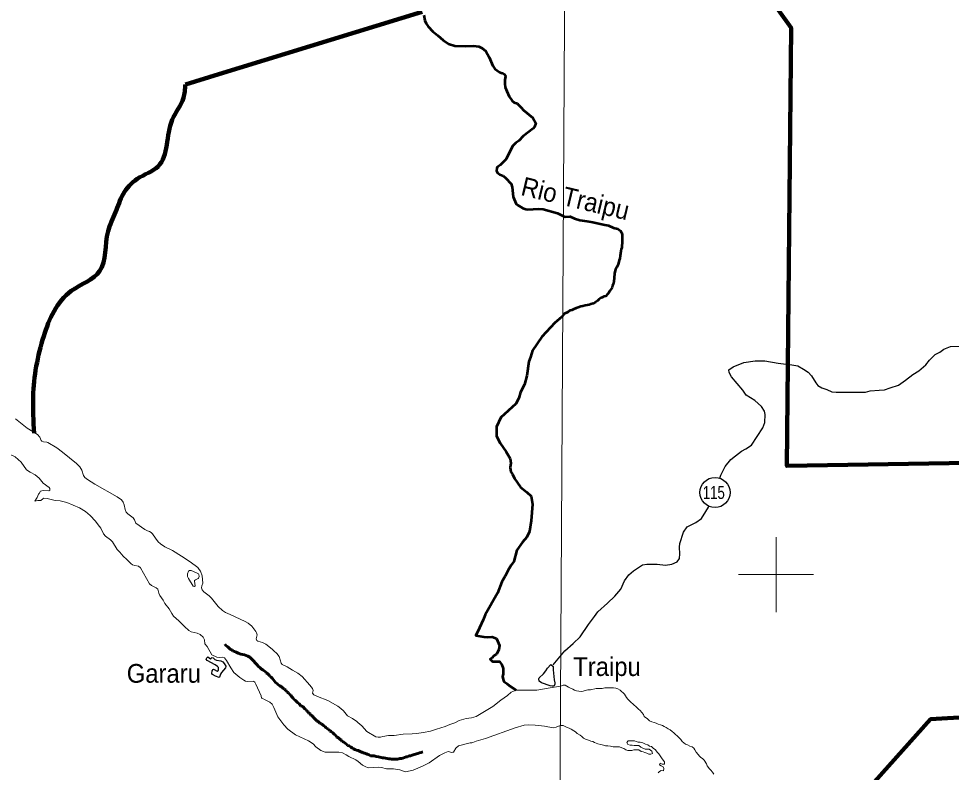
# Model space of a CAD drawing. Extents: x 553962 to 842807, y 8883888 to 9032388.
# Drawn here: x 704795 to 729677, y 8894722 to 8914830 of the extents above; entities that cross this region are included whole.
import ezdxf
from ezdxf.enums import TextEntityAlignment as Align

# ---------------------------------------------------------------- set-up
doc = ezdxf.new("R2010")
doc.units = 0
doc.header["$LTSCALE"] = 200
doc.linetypes.add('LONG_DASH_SHORT_DASH', pattern=[9.9, 6, -1.2, 1.5, -1.2])
for name, color, linetype, lineweight in [('1', 7, 'Continuous', 13), ('12', 7, 'Continuous', 25), ('2', 7, 'Continuous', 13), ('21', 7, 'Continuous', 25), ('24', 7, 'Continuous', 25), ('25', 7, 'Continuous', 13), ('48', 7, 'Continuous', 25), ('7', 7, 'LONG_DASH_SHORT_DASH', 60), ('9', 7, 'Continuous', 90)]:
    doc.layers.add(name, color=color, linetype=linetype, lineweight=lineweight)
doc.layers.add('41', color=7, linetype='Continuous')
doc.layers.add('49', color=7, linetype='Continuous')

msp = doc.modelspace()

# ---------------------------------------------------------------- linework, layer by layer
at = {"layer": '1'}
msp.add_lwpolyline([(719978.9, 9023574.5), (719561.6, 8949232.2), (719215.6, 8890710.6)], dxfattribs=at)
at = {"layer": '12'}
for points in [[(727039.6, 8904864.2), (727284.1, 8904868.9), (727391.1, 8904868.7), (727508.4, 8904899), (727747.9, 8904919), (727890.6, 8904928.9), (728048.7, 8904984.6), (728268, 8905055.5), (728451.9, 8905187.7), (728651.2, 8905340.1), (728809.4, 8905436.6), (728993.4, 8905594.2), (729095.8, 8905716.2), (729249.1, 8905868.8), (729371.7, 8905934.8), (729473.8, 8906011), (729657.5, 8906082), (729896.9, 8906091.7)], [(723502.8, 8902567), (723531.6, 8902649.7), (723639.5, 8902883.8), (723793, 8903072), (723920.7, 8903168.5), (724079.1, 8903290.5), (724191.4, 8903356.5), (724349.7, 8903453), (724652, 8903916), (724698.3, 8904058.6), (724714.4, 8904272.5), (724689.2, 8904354.1), (724613.3, 8904481.5), (724430.5, 8904644.9), (724201.8, 8904787.9), (724110.5, 8904915.5), (723811.3, 8905272.6), (723745.5, 8905389.9), (723740.7, 8905461.2), (723858.1, 8905542.5), (724143.8, 8905659.1), (724444.6, 8905699.3), (724704.4, 8905698.9), (725060.7, 8905637.1), (725417.2, 8905595.7), (725585.2, 8905564.8), (725732.6, 8905477.9), (725859.7, 8905396.2), (725945.9, 8905304.3), (726062.4, 8905115.6), (726113.1, 8905039.1), (726219.8, 8904977.8), (726352.1, 8904931.7), (726489.4, 8904870.3), (726601.5, 8904865), (727039.6, 8904864.2)], [(719051.7, 8897586.9), (719362.5, 8897965.7), (719587.4, 8898163.9), (719771.5, 8898341.9), (719996.8, 8898667.5), (720160.6, 8898881.1), (720247.7, 8899003.2), (720508.3, 8899237.1), (720697.5, 8899420.1), (720856.1, 8899608.3), (720953.7, 8899827.2), (721076.6, 8899989.9), (721194.2, 8900101.8), (721434.2, 8900254.2), (721551.4, 8900279.4), (721826.5, 8900273.8), (722050.5, 8900248), (722223.9, 8900278.2), (722366.7, 8900339.1), (722428.2, 8900425.6), (722433.7, 8900552.9), (722424.2, 8900726.1), (722429.7, 8900828), (722532.7, 8901133.4), (722624.9, 8901275.9), (722864.7, 8901387.5), (723007.8, 8901494.2), (723130.7, 8901677.4), (723197.4, 8901799.6), (723209.3, 8901823.1)]]:
    msp.add_lwpolyline(points, dxfattribs=at)
at = {"layer": '2'}
for p, q in [((725000, 8899000), (725000, 8901000)), ((724000, 8900000), (726000, 8900000))]:
    msp.add_line(p, q, dxfattribs=at)
at = {"layer": '21'}
for points in [[(710323, 8897547.4), (710310.6, 8897510.9), (710262.7, 8897448.5), (710205.4, 8897388.1), (710179.6, 8897340.9), (710149.4, 8897265.1), (710140.8, 8897256.9), (710043.9, 8897288.4), (709961.7, 8897329.1), (709947.6, 8897363.1), (709961.6, 8897429.2), (709984.2, 8897470), (709989.6, 8897472.6), (710012.7, 8897467.5), (710090.3, 8897425.2), (710122.4, 8897447.6), (710126, 8897519.8), (710103.3, 8897545.3), (710035.6, 8897588.8), (709826.1, 8897706.4), (709795.6, 8897744), (709810.8, 8897781.5), (709838, 8897800.1), (709914.9, 8897754.6), (709934.2, 8897760.9), (709942.3, 8897776.2), (709957.1, 8897785.6), (709980.8, 8897774.5), (710029.3, 8897733.8), (710072, 8897710.7), (710184.3, 8897701.5), (710239.2, 8897671.8), (710278.2, 8897623.4), (710322, 8897552.2)], [(718993.1, 8897599.9), (719057.4, 8897544.6), (719055.9, 8897461.4), (719085.3, 8897192.5), (719103.1, 8897108.8), (719098.1, 8897076.1), (719079.4, 8897033), (719065.5, 8897020), (719028.2, 8897020.1), (718974.7, 8897034.1), (718746.2, 8897111.7), (718679.7, 8897153.1), (718671.6, 8897221.2), (718685, 8897240.1), (718799.2, 8897348.2), (718862.4, 8897430.9), (718906.6, 8897502.9)]]:
    msp.add_lwpolyline(points, close=True, dxfattribs=at)
at = {"layer": '24', "lineweight": 53}
for points in [[(715607.3, 8914926.5), (715630.8, 8914782.1), (715664.2, 8914698.4), (715720.4, 8914621.3), (715841.4, 8914484.8), (715976.3, 8914382.9), (716121.9, 8914251.7), (716262.7, 8914158.2), (716430.6, 8914102.4), (716723.3, 8914098.2), (716931, 8914106.3), (717067.3, 8914089.8), (717160, 8914040), (717258.6, 8913960.8), (717350.2, 8913798.9), (717444.9, 8913569.6), (717500.7, 8913495.3), (717620.4, 8913403.7), (717696.9, 8913374.6), (717753.4, 8913338.3), (717771.3, 8913315.3), (717779.7, 8913284.7), (717767.4, 8913198.7), (717765.2, 8913088.6), (717776, 8913003.3), (717816.4, 8912891.5), (717881.6, 8912752), (717959.7, 8912633.8), (718012.2, 8912595.1), (718103.9, 8912566), (718108.4, 8912552.9), (718200.6, 8912462.7), (718263.8, 8912388), (718510.9, 8912180.7), (718595.9, 8912042.5), (718559.6, 8911942), (718525.1, 8911895.3), (718256.7, 8911695.7), (718139.8, 8911569.1), (718058.8, 8911518.2), (717971, 8911425.9), (717799.8, 8911079.5), (717637.2, 8910919.9), (717559.9, 8910863.9), (717548.7, 8910844.9), (717546.6, 8910765.8), (717564.2, 8910723.9), (717629.5, 8910673.2), (717717.9, 8910632.5), (717786.1, 8910583.9), (717932.5, 8910426.1), (717961.9, 8910338.5), (717987.1, 8910076.6), (718063.3, 8909892.7), (718110.2, 8909851.7), (718240.9, 8909774.5), (718323.8, 8909744.9), (718380.9, 8909735.3), (718665.9, 8909753.1), (718783.6, 8909747.4), (719169.5, 8909639.4), (719326.4, 8909556.3)], [(719326.4, 8909556.3), (719371.3, 8909542.5), (719371.3, 8909542.5), (719504.5, 8909548.1), (719504.5, 8909548.1), (719504.5, 8909548.1), (719626.5, 8909498.2)], [(719626.5, 8909498.2), (719765.2, 8909453.8), (719765.2, 8909453.8), (719765.2, 8909453.8), (719765.2, 8909453.8), (719948.4, 8909426.1), (719948.4, 8909426.1), (719948.4, 8909426.1), (720114.8, 8909398.4), (720114.8, 8909398.4), (720114.8, 8909398.4), (720392.3, 8909337.4), (720392.3, 8909337.4), (720392.3, 8909337.4), (720392.3, 8909337.4), (720531, 8909309.6), (720531, 8909309.6), (720531, 8909309.6), (720664.2, 8909248.6), (720780.7, 8909226.5), (720848.9, 8909167.8), (720879.1, 8909126.9), (720899.1, 8909075.8), (720898.7, 8909024.9), (720898.3, 8908963.8), (720892.8, 8908897.6), (720892.3, 8908831.3), (720886.9, 8908780.4), (720886.5, 8908724.4), (720865.8, 8908678.7), (720860.4, 8908622.7), (720854.9, 8908561.6), (720844.3, 8908500.6), (720828.6, 8908434.4), (720818, 8908383.6), (720797.2, 8908307.3), (720781.6, 8908256.4), (720750.7, 8908200.6), (720714.6, 8908139.7), (720699, 8908078.7), (720693.5, 8908027.8), (720680.1, 8907917.9)], [(720680.1, 8907917.9), (720671.8, 8907819.1), (720661.2, 8907768.2), (720640.5, 8907712.3), (720624.9, 8907661.5), (720594, 8907605.6), (720558.1, 8907560), (720532.3, 8907509.3), (720496.4, 8907468.7), (720460.5, 8907428.2), (720409.6, 8907413.3), (720363.7, 8907393.2), (720312.7, 8907373.1), (720276.8, 8907337.7), (720241, 8907302.3), (720179.7, 8907267), (720118.4, 8907231.8), (720062.3, 8907216.8), (720016.4, 8907196.8), (719965.5, 8907181.8), (719909.5, 8907177.1), (719843.3, 8907162.2), (719792.3, 8907152.3), (719720.9, 8907122.2), (719664.9, 8907107.3), (719603.6, 8907077.1), (719552.6, 8907057.1), (719496.6, 8907042.2), (719445.4, 8907001.8), (719343.4, 8906951.5), (719283.6, 8906877)], [(719283.6, 8906877), (719100.8, 8906711), (718751.9, 8906345.6), (718502.7, 8905980.3), (718452.8, 8905797.7), (718403, 8905681.4), (718353.1, 8905299.5), (718286.7, 8905067), (718187, 8904867.8), (718137.2, 8904701.7), (718054.1, 8904552.2), (717859.9, 8904374.3), (717854.7, 8904369.6)], [(717854.7, 8904369.6), (717655.3, 8904186.9), (717539, 8903937.8), (717539, 8903688.8), (717638.7, 8903506.1), (717804.9, 8903273.6), (717904.6, 8903091), (717921.2, 8902974.7), (717904.6, 8902858.5), (717921.2, 8902742.3), (717971.1, 8902675.9), (718020.9, 8902559.6), (718187, 8902327.1), (718353.2, 8902194.3), (718469.5, 8902094.7), (718502.7, 8901878.8), (718469.5, 8901430.4), (718419.6, 8901148.2), (718353.2, 8900998.7), (718236.8, 8900865.9), (718087.3, 8900650), (718004.2, 8900351.1), (717937.8, 8900251.5), (717854.7, 8900118.6), (717771.7, 8899952.6), (717688.6, 8899803.1), (717572.3, 8899504.2), (717240, 8898923), (717190.1, 8898790.2), (717090.4, 8898574.3), (716990.8, 8898375.1), (717206.8, 8898341.9), (717289.8, 8898325.2), (717422.7, 8898341.9), (717539, 8898292), (717622.1, 8898109.4), (717605.5, 8897993.1), (717539, 8897876.9), (717472.6, 8897827.1), (717422.7, 8897777.3), (717372.9, 8897744.1), (717439.4, 8897677.6), (717622.1, 8897677.6), (717688.6, 8897594.6), (717721.8, 8897495), (717721.8, 8897395.3), (717721.8, 8897345.5), (717705.2, 8897279.1), (717721.8, 8897196.1), (717738.4, 8897146.3), (717821.5, 8897096.4), (717888, 8897030), (718070.7, 8896913.8)]]:
    msp.add_lwpolyline(points, dxfattribs=at)
at = {"layer": '25'}
for points in [[(704709.8, 8904149.5), (705025.3, 8903904.5), (705294.1, 8903731.4), (705355.9, 8903661.9), (705397.8, 8903579.9), (705416.3, 8903559.4), (705456.6, 8903537.1), (705545.2, 8903528.8), (705574.6, 8903518.8), (705812.1, 8903380.7), (705964.1, 8903265.1), (706335.8, 8902958.3), (706429, 8902870.5), (706478.4, 8902782.6), (706522.3, 8902644.6), (706561.4, 8902592.6), (706627.5, 8902537.3), (706829.4, 8902410.4), (707426.7, 8902069.6), (707536.7, 8901989.7), (707580.8, 8901930.1), (707613.5, 8901857.8), (707638, 8901734), (707661.4, 8901666.3), (707707.1, 8901616.1), (707849, 8901513.6), (707889.3, 8901456.4), (707921.2, 8901374.1), (708164.6, 8901203.2), (708234, 8901164.4), (708282.6, 8901144)], [(705417, 8902230.5), (705468.7, 8902243.1), (705601.7, 8902236.3), (705626.1, 8902249.9), (705630.1, 8902294), (705613.1, 8902318.7), (705450.5, 8902433.4), (705338.6, 8902571.8), (705237.8, 8902662.7), (705098.5, 8902732.8), (705008.4, 8902794.2), (704859.8, 8902995.3), (704700.7, 8903136.3), (704418.9, 8903273.5)], [(705223.5, 8901956.6), (705285.9, 8902055.5), (705327.2, 8902145.4), (705340, 8902163.9), (705340, 8902163.9)], [(705340, 8902163.9), (705380.2, 8902221.5), (705417, 8902230.5)], [(706917, 8901328.8), (706845.7, 8901419), (706706.3, 8901570.6), (706577.5, 8901683.7), (706418, 8901776), (706077.6, 8901924.8), (705902.1, 8901964.8), (705769.4, 8901975.3), (705559.8, 8902024.1), (705462.6, 8902034.1), (705436.9, 8902022.7), (705383.9, 8901976.1), (705305.7, 8901975.9), (705223.5, 8901956.6)], [(708884.8, 8898960.2), (708812.9, 8899081.1), (708692, 8899230.3), (708649.9, 8899313.3), (708562.2, 8899440.2), (708534.2, 8899502.9), (708503.8, 8899608.4), (708465.9, 8899644.1), (708336.8, 8899710.3), (708284.4, 8899750.1), (708047.8, 8900175.7), (707990.8, 8900226.5), (707897.1, 8900236.8), (707831, 8900260), (707784.3, 8900295.7), (707679.2, 8900403.7), (707579.3, 8900485.4), (707498.4, 8900600.3), (707426.9, 8900668.2), (707296.2, 8900870.2), (707244.9, 8900923.6), (707114.9, 8901025.9), (707060.8, 8901088.8), (706991.1, 8901234.8), (706917, 8901328.8)], [(708282.6, 8901144), (708331.2, 8901123.5), (708369.6, 8901088.6), (708444.9, 8900971.6), (708520.8, 8900871.2), (708577.2, 8900819.4), (708690.2, 8900735.5), (708901.9, 8900638.8), (709137.2, 8900490.7)], [(709137.2, 8900490.7), (709372.6, 8900342.6), (709571.9, 8900187.3), (709610.7, 8900136.5)], [(709610.7, 8900136.5), (709649.5, 8900085.8), (709687.8, 8899966.6), (709696.9, 8899867.4)], [(709696.9, 8899867.4), (709706, 8899768.3), (709680, 8899695), (709673.6, 8899642.5), (709691.5, 8899588), (709738.8, 8899535.9), (709875.6, 8899429.5), (709875.6, 8899429.5), (709939.8, 8899367.7), (710112.9, 8899145), (710229.9, 8899043.2), (710316.3, 8898983), (710434.5, 8898930.1)], [(709950.2, 8897853.8), (709826.5, 8898078.7), (709765, 8898154.3), (709755.6, 8898257.5), (709714.4, 8898328.8), (709634.6, 8898396.5), (709559.8, 8898439.4), (709395, 8898473.4), (709333.8, 8898506.8), (709214.9, 8898614.3), (709070.8, 8898765.5), (708925, 8898892.5), (708884.8, 8898960.2)], [(710434.5, 8898930.1), (710835, 8898750.5), (710918.4, 8898699.6), (711013.8, 8898623.8), (711070, 8898553.2)], [(711070, 8898553.2), (711126.2, 8898482.6), (711144.3, 8898448), (711158.3, 8898389.2), (711130.3, 8898282.3), (711152.8, 8898240), (711175.8, 8898222.2), (711302.1, 8898183.8), (711391.3, 8898138.3), (711554.3, 8898011), (711603.7, 8897966)], [(711603.7, 8897966), (711680.2, 8897896.3), (711746, 8897808.5), (711799.4, 8897633.4), (711822.1, 8897601.2), (711960, 8897533.9), (712103.8, 8897448.7)], [(710692.4, 8897249.1), (710533.9, 8897388.5), (710451.3, 8897511.8), (710342.9, 8897708), (710286.4, 8897777.2), (710220.4, 8897794.9), (710145.3, 8897789.3), (710079.5, 8897794.7), (709950.2, 8897853.8)], [(712103.8, 8897448.7), (712242.6, 8897366.3), (712359.3, 8897283.4), (712565.7, 8897048.4), (712631.8, 8896958.1), (712647.9, 8896909.4), (712637.9, 8896831.9), (712665.2, 8896790.9), (712768.3, 8896741.4), (713044.9, 8896638.8), (713311.2, 8896489.3), (713385.5, 8896424.1)], [(711124.5, 8897078.8), (711093, 8897127.9), (711068.7, 8897147.8), (711049.5, 8897152.8), (710908.8, 8897146.9), (710849.4, 8897155.7), (710797.6, 8897180.7), (710692.4, 8897249.1)], [(712525.7, 8895564.3), (712179.3, 8895726.8), (711977.5, 8895873.7), (711872.3, 8895986), (711707.5, 8896200.3), (711600.3, 8896454.3), (711553.8, 8896536.9), (711494.9, 8896598.8), (711354.3, 8896661.8), (711292.1, 8896701.3), (711270.5, 8896704.9), (711261.3, 8896763.5), (711124.5, 8897078.8)], [(716671.9, 8896141.4), (716736, 8896160), (716876.8, 8896172.9), (716996.8, 8896216.3), (717443.2, 8896481.3), (717658.9, 8896651.8), (717833.2, 8896772.8), (717934, 8896865.6), (718070.7, 8896913.8), (718220.3, 8896913.8), (718619, 8896913.8), (718918.1, 8896963.6), (719252.2, 8897020.3)], [(719252.2, 8897020.3), (719320.1, 8897049.2), (719376, 8897048.8), (719416.5, 8897018), (719467.2, 8896997.3), (719517.9, 8896971.5), (719578.7, 8896940.5), (719624.3, 8896914.8), (719680.1, 8896894), (719736.1, 8896888.6), (719797.1, 8896883.1), (719858.1, 8896887.8), (719909.1, 8896907.8), (719980.4, 8896922.7), (720046.6, 8896927.3), (720199.4, 8896962), (720255.3, 8896961.7), (720306.2, 8896961.3), (720362.2, 8896961), (720428.4, 8896980.9), (720479.3, 8896980.6), (720540.3, 8896980.2), (720606.4, 8896979.8), (720667.5, 8896979.4), (720723.3, 8896968.8), (720779.1, 8896948.1), (720845, 8896917.1), (720880.4, 8896881.2), (720920.8, 8896845.3), (720956.2, 8896809.4)], [(720956.2, 8896809.4), (720981.3, 8896763.4), (721006.4, 8896717.4), (721046.8, 8896676.4), (721082.2, 8896635.4), (721127.7, 8896594.4), (721188.3, 8896538), (721289.5, 8896455.8), (721329.8, 8896404.6), (721375.3, 8896368.7), (721420.8, 8896322.5), (721461, 8896261.2), (721486.2, 8896215.2), (721567.1, 8896148.4), (721627.8, 8896097.1), (721683.5, 8896071.3), (721749.5, 8896050.5), (721805.3, 8896034.8), (721856, 8896009), (721916.9, 8895988.3), (721972.7, 8895967.5), (722018.4, 8895946.9), (722069, 8895921.1), (722119.7, 8895885.1), (722175.4, 8895854.2), (722231, 8895808), (722271.5, 8895772), (722312, 8895741.2), (722367.5, 8895689.9), (722402.9, 8895654), (722463.5, 8895597.6), (722493.7, 8895546.5), (722584.8, 8895474.6), (722635.5, 8895453.9), (722701.4, 8895417.8), (722762.3, 8895402.1), (722802.7, 8895366.2), (722832.9, 8895320.2), (722873.2, 8895263.9), (722923.6, 8895197.3), (722953.8, 8895151.3), (722994.3, 8895120.5), (723039.9, 8895089.6), (723085.4, 8895048.6), (723145.7, 8894951.4), (723165.7, 8894895.3), (723221.1, 8894818.5), (723261.6, 8894782.6), (723301.9, 8894726.3), (723337.1, 8894675.1)], [(713385.5, 8896424.1), (713459.8, 8896359), (713569.8, 8896225.6), (713696.9, 8896155.1), (713818.3, 8896075.1), (713842, 8896053.8)], [(715944.9, 8895871), (716177.3, 8895944.3), (716297, 8895998.6), (716434.9, 8896046.3), (716544.4, 8896104.3), (716671.9, 8896141.4)], [(713842, 8896053.8), (713946.1, 8895960.1), (714080.1, 8895815.7), (714321.1, 8895672.2), (714384.5, 8895659.7), (714451.9, 8895662.4), (714514.6, 8895674.6)], [(719242.1, 8895974.6), (719137.8, 8895926.7), (719051.9, 8895910.8), (718819, 8895950.7), (718570.6, 8895982.3), (718406.7, 8895992.1), (718284.1, 8895976.8), (718038.4, 8895905.8), (717250.7, 8895623.3), (716998.4, 8895554.6), (716915, 8895518.1), (716881.8, 8895513.8)], [(721516.7, 8895476.3), (721445.7, 8895507.4), (721379.7, 8895523.1), (721323.7, 8895523.4), (721273, 8895544.1), (721222.2, 8895559.7), (721151.1, 8895560.2), (721054.4, 8895560.8), (721023.6, 8895520.3), (721043.6, 8895469.2), (721104.5, 8895443.3), (721160.4, 8895443), (721211.3, 8895442.7), (721277.4, 8895442.2), (721343.5, 8895436.7), (721394.1, 8895395.6), (721444.7, 8895364.7), (721505.6, 8895344), (721561.5, 8895338.5), (721612.4, 8895338.2), (721688.3, 8895286.8), (721708.2, 8895225.5), (721657.3, 8895210.6), (721606.4, 8895210.9), (721555.7, 8895231.6), (721499.9, 8895252.3), (721454.2, 8895273), (721398.3, 8895278.4), (721342.7, 8895319.6), (721276.6, 8895325.1), (721205.3, 8895320.4), (721154.4, 8895305.5), (721098.4, 8895300.7), (721042.5, 8895301.1), (720996.9, 8895326.9), (720941.1, 8895357.8), (720890.4, 8895378.5), (720824.4, 8895399.3), (720773.6, 8895399.6), (720722.7, 8895399.9), (720656.6, 8895405.4), (720580.4, 8895421.2), (720509.3, 8895426.8), (720448.2, 8895427.2), (720397.5, 8895447.9), (720326.5, 8895468.7), (720250.3, 8895484.5), (720158.9, 8895515.6), (720113.3, 8895541.4), (720062.6, 8895557), (719996.6, 8895577.8), (719920.5, 8895608.8), (719864.8, 8895634.7), (719819.3, 8895675.7), (719778.8, 8895711.6), (719692.7, 8895758), (719647.2, 8895799.1), (719606.7, 8895829.9), (719535.8, 8895876.2), (719480.1, 8895902), (719429.3, 8895917.6), (719373.6, 8895948.5), (719317.8, 8895969.3), (719266.9, 8895969.6), (719242.1, 8895974.6)], [(714514.6, 8895674.6), (714664.7, 8895703.8), (714810.4, 8895708.8), (715055.3, 8895739.1), (715289.1, 8895748.2), (715407.8, 8895761.9)], [(715407.8, 8895761.9), (715591.5, 8895783.2), (715777.5, 8895818.2), (715944.9, 8895871)], [(713532.7, 8895186.2), (713435.1, 8895242.8), (713335.4, 8895258.7), (712968.6, 8895262), (712859.7, 8895301.9), (712725.3, 8895401.6), (712648.5, 8895483.1), (712525.7, 8895564.3)], [(716881.8, 8895513.8), (716841.2, 8895508.6), (716533, 8895427), (716458.2, 8895365.9), (716394.5, 8895260), (716374.9, 8895256.9)], [(721852.2, 8894705), (721893.1, 8894740.4), (721934, 8894770.7), (721995, 8894765.2), (722010.6, 8894821.2), (721985.5, 8894867.2), (721934.8, 8894893), (721889.3, 8894923.8), (721909.9, 8894969.5), (721960.6, 8894943.7), (722021.6, 8894943.3), (722027.1, 8895004.4), (721986.8, 8895050.5), (721946.5, 8895106.8), (721911.2, 8895163.1), (721871, 8895219.4), (721825.5, 8895260.4), (721780.1, 8895321.8), (721719.4, 8895368.1), (721679, 8895409.1), (721628.2, 8895424.7), (721577.6, 8895455.6), (721516.7, 8895476.3)], [(715039.1, 8894760), (714963.6, 8894786.5), (714790.6, 8894820), (714606.1, 8894818.8), (714473.2, 8894853.3), (714404.1, 8894859.6), (714116.9, 8894843.6), (714034.5, 8894876.8), (713967, 8894916.7), (713850.5, 8895013.2), (713789.1, 8895053.9), (713604, 8895144.8), (713532.7, 8895186.2)], [(716374.9, 8895256.9), (716350.2, 8895253.1), (716257.5, 8895274.6), (716162.3, 8895243), (716023.3, 8895172.8), (715744.1, 8894976.4), (715570.5, 8894886.6), (715322, 8894784.1), (715114.6, 8894733.5), (715039.1, 8894760)]]:
    msp.add_lwpolyline(points, dxfattribs=at)
msp.add_lwpolyline([(709580.3, 8899889.8), (709596.2, 8899906.3), (709606, 8899943.5), (709599.7, 8899997.3), (709588.6, 8900017.3), (709459.5, 8900083.7), (709393.7, 8900104.9), (709351.6, 8900105.7), (709323, 8900086.1), (709294.9, 8900014.3), (709301.9, 8899949.1), (709327.1, 8899890.5), (709454.5, 8899688.2), (709485.7, 8899677.3), (709503.8, 8899701.2), (709483.4, 8899821.2), (709487.6, 8899841.5), (709510.1, 8899860.5)], close=True, dxfattribs=at)
at = {"layer": '48'}
msp.add_circle((723371.8, 8902188.1), 401.3, dxfattribs=at)
at = {"layer": '7'}
for points in [[(711474.4, 8897314.1), (711433.6, 8897355), (711398, 8897378), (711370, 8897413.8), (711308.9, 8897454.7), (711270.7, 8897477.7), (711230, 8897521.1), (711189.3, 8897549.2), (711148.6, 8897600.3), (711112.9, 8897631), (711056.9, 8897694.9), (711016.2, 8897746.1), (710965.3, 8897792.1), (710911.8, 8897817.6), (710817.7, 8897856), (710718.5, 8897873.8), (710647.2, 8897904.5), (710598.8, 8897925), (710555.6, 8897945.4), (710507.2, 8897965.9), (710481.8, 8897986.3), (710448.7, 8898001.7), (710413.1, 8898034.9), (710374.9, 8898073.2), (710334.2, 8898098.8), (710296.3, 8898144.4)], [(712701.2, 8896140.8), (712675.8, 8896166.4), (712632.5, 8896220.1), (712599.4, 8896243.1), (712581.6, 8896276.3), (712546, 8896294.2), (712525.6, 8896327.4), (712487.4, 8896347.9), (712467.1, 8896388.8), (712431.4, 8896414.3), (712375.4, 8896475.7), (712327.1, 8896498.7), (712276.2, 8896547.2), (712230.3, 8896585.6), (712176.9, 8896636.7), (712146.3, 8896664.8), (712110.7, 8896708.3), (712075.1, 8896746.6), (712052.2, 8896784.9), (712016.5, 8896805.4), (711996.2, 8896843.7), (711960.5, 8896861.6), (711924.9, 8896910.2), (711889.3, 8896928.1), (711866.3, 8896958.8), (711830.7, 8896976.7), (711795.1, 8897009.9), (711759.5, 8897027.8), (711718.7, 8897061), (711695.8, 8897081.5), (711657.6, 8897112.1), (711619.5, 8897158.2), (711594, 8897186.3), (711555.8, 8897232.3), (711532.9, 8897257.8), (711497.3, 8897291.1), (711474.4, 8897314.1)], [(715172.3, 8895138.8), (715134.1, 8895136.3), (715085.8, 8895115.8), (715047.6, 8895103.1), (715004.4, 8895095.4), (714963.7, 8895087.7), (714935.7, 8895082.6), (714900.1, 8895077.5), (714841.5, 8895077.5), (714803.3, 8895077.5), (714762.7, 8895077.5), (714739.7, 8895077.5), (714701.6, 8895080), (714673.6, 8895082.6), (714625.2, 8895090.3), (714582, 8895097.9), (714541.3, 8895105.6), (714503.1, 8895113.3), (714464.9, 8895120.9), (714431.8, 8895128.6), (714391.1, 8895136.3), (714332.6, 8895143.9), (714279.2, 8895159.3), (714230.8, 8895166.9), (714185, 8895166.9), (714144.3, 8895187.4), (714096, 8895205.3), (714055.2, 8895220.6), (714034.9, 8895225.7), (714004.3, 8895241.1), (713984, 8895246.2), (713945.8, 8895264.1), (713922.9, 8895269.2), (713889.8, 8895289.6), (713851.6, 8895307.5), (713808.4, 8895310.1), (713762.6, 8895328), (713732, 8895345.9), (713693.9, 8895376.5), (713653.1, 8895391.9), (713612.4, 8895425.1), (713569.2, 8895440.4), (713541.2, 8895471.1), (713503, 8895496.7), (713467.3, 8895527.3), (713429.2, 8895547.8), (713403.7, 8895581), (713370.6, 8895601.5), (713324.8, 8895642.4), (713273.9, 8895670.5), (713248.5, 8895716.5), (713210.3, 8895739.5), (713177.2, 8895775.3), (713131.4, 8895811.1), (713098.3, 8895831.5), (713057.6, 8895869.9), (713032.1, 8895885.2), (712991.4, 8895918.4), (712968.5, 8895933.8), (712930.3, 8895972.1), (712871.8, 8896020.7), (712828.5, 8896033.5), (712787.8, 8896074.3), (712747.1, 8896094.8), (712701.2, 8896140.8)], [(715575.1, 8895269.4), (715574.3, 8895269.2), (715533.6, 8895253.9), (715487.8, 8895238.5), (715444.5, 8895225.8), (715347.8, 8895195.1), (715294.4, 8895177.2), (715248.6, 8895164.4), (715200.3, 8895159.3), (715172.3, 8895138.8)]]:
    msp.add_lwpolyline(points, dxfattribs=at)
at = {"layer": '9'}
for p, q in [((710134.6, 8913345.1), (715561.4, 8915010.8)), ((709242.2, 8913071.2), (710135.7, 8913345.4))]:
    msp.add_line(p, q, dxfattribs=at)
for points in [[(741371.9, 8898310.2), (736775.3, 8899194.4), (730163.4, 8902976.8), (725291.2, 8902898), (725401.2, 8914588.3), (719613.1, 8922670.1)], [(724638.9, 8891123.6), (729122.2, 8896139.1), (740717.5, 8896813.6), (741371.9, 8898310.2)]]:
    msp.add_lwpolyline(points, dxfattribs=at)
msp.add_spline([(705207.9, 8903769.6), (705180.7, 8904747.4), (705463.8, 8906360), (706198.7, 8907564.6), (706955.5, 8908091.1), (707178.8, 8909156.3), (707379.5, 8909664.2), (707580.3, 8910146.8), (707959.3, 8910554.8), (708516.4, 8910888.1), (708891.3, 8912131.7), (709193.2, 8912716.3), (709242.2, 8913071.2)], degree=3, dxfattribs=at)

# ---------------------------------------------------------------- texts
at = {"layer": '41', "width": 0.95}
for s, p in [('Traipu', (719591.1, 8897292.6)), ('Gararu', (707678.8, 8897112.8))]:
    msp.add_text(s, height=500, dxfattribs=at).set_placement(p)
at = {"layer": '48', "width": 0.75}
msp.add_text('115', height=350, dxfattribs=at).set_placement((723340.2, 8902014.7), align=Align.CENTER)
at = {"layer": '49', "width": 0.95}
msp.add_text('Rio Traipu', height=500, rotation=346.601, dxfattribs=at).set_placement((719591, 8909789.6), align=Align.CENTER)

doc.saveas('drawing.dxf')
